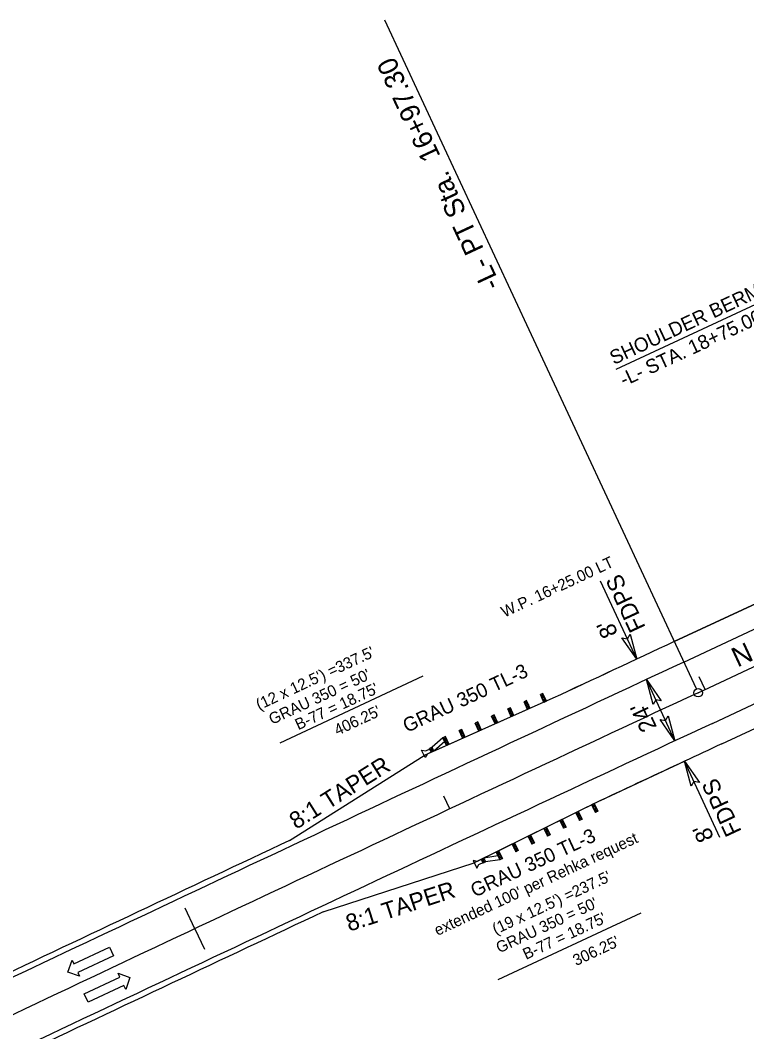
# Model space of a CAD drawing. Extents: x 2320644 to 2322941, y 921672 to 923041.
# Drawn here: x 2321170.5 to 2321428.4, y 921958.1 to 922316.8 of the extents above; entities that cross this region are included whole.
import ezdxf

# ---------------------------------------------------------------- set-up
doc = ezdxf.new("R2010")
doc.units = 0
for name, color, linetype in [('Matchline', 7, 'Continuous'), ('Matchline Text', 7, 'Continuous'), ('Prop Approach Slab', 7, 'Continuous'), ('Prop Conc Shoulder Berm Gutter', 7, 'Continuous'), ('Prop Dimension', 7, 'Continuous'), ('Prop EOT', 7, 'Continuous'), ('Prop Guardrail', 7, 'Continuous'), ('Prop Horizontal Alignment', 7, 'Continuous'), ('Prop Horizontal Alignment Tick Small', 7, 'Continuous'), ('Prop Lane Arrow CELL', 7, 'Continuous'), ('Prop North Arrow NAD83 for Plan Sheets CELL', 7, 'Continuous'), ('Sheet Sticker Exception Certification CELL', 7, 'Continuous'), ('Skimmer Basin Both CELL', 7, 'Continuous')]:
    doc.layers.add(name, color=color, linetype=linetype)

msp = doc.modelspace()

# ---------------------------------------------------------------- linework, layer by layer
at = {"layer": 'Matchline'}
msp.add_line((2321411.13, 922078.36), (2321804.4, 922261.67), dxfattribs=at)
msp.add_arc((2342535.16, 876759.76), 50000, 114.991298, 115.303471, dxfattribs=at)
at = {"layer": 'Prop Approach Slab'}
for p, q in [((2321406.06, 922089.24), (2321799.33, 922272.55)), ((2321416.2, 922067.48), (2321809.47, 922250.79))]:
    msp.add_line(p, q, dxfattribs=at)
for radius in [50012, 49988]:
    msp.add_arc((2342535.16, 876759.76), radius, 114.991298, 115.303471, dxfattribs=at)
at = {"layer": 'Prop Conc Shoulder Berm Gutter'}
for p, q in [((2321402.68, 922096.49), (2321484.21, 922134.49)), ((2321419.58, 922060.23), (2321500.59, 922097.99)), ((2321359.57, 922076.37), (2321313.84, 922056.08)), ((2321266.1, 922025.94), (2321313.84, 922056.08)), ((2321376.51, 922040.13), (2321331.66, 922018.04)), ((2321278.01, 922000.6), (2321331.66, 922018.04))]:
    msp.add_line(p, q, dxfattribs=at)
for centre, radius, start, end in [((2342535.16, 876759.76), 50020, 114.991298, 115.045792), ((2342535.16, 876759.76), 49980, 114.991298, 115.008116), ((2342522.93, 876785.96), 49951.09, 115.008105, 115.045803), ((2342535.16, 876759.76), 50014, 115.167259, 115.303471), ((2342535.16, 876759.76), 49986, 115.167259, 115.303471)]:
    msp.add_arc(centre, radius, start, end, dxfattribs=at)
at = {"layer": 'Prop Dimension'}
msp.add_line((2321410.5, 922079.72), (2321299.98, 922316.83), dxfattribs=at)
msp.add_circle((2321411.13, 922078.36), 1.5, dxfattribs=at)
at = {"layer": 'Prop EOT'}
for p, q in [((2321356.05, 922078.09), (2321355.14, 922077.68)), ((2321356.35, 922074.94), (2321355.14, 922077.68)), ((2321355.14, 922077.68), (2321356.66, 922076.72)), ((2321355.74, 922076.31), (2321356.05, 922078.09)), ((2321357.27, 922075.35), (2321356.05, 922078.09)), ((2321359.59, 922076.38), (2321316.86, 922057.41)), ((2321350.27, 922075.58), (2321349.36, 922075.17)), ((2321350.59, 922072.38), (2321349.36, 922075.17)), ((2321349.36, 922075.17), (2321350.89, 922074.18)), ((2321349.97, 922073.78), (2321350.27, 922075.58)), ((2321350.89, 922074.18), (2321349.97, 922073.78)), ((2321351.51, 922072.79), (2321350.27, 922075.58)), ((2321350.89, 922074.18), (2321350.59, 922072.38)), ((2321356.66, 922076.72), (2321355.74, 922076.31)), ((2321356.35, 922074.94), (2321355.74, 922076.31)), ((2321355.74, 922076.31), (2321357.27, 922075.35)), ((2321356.66, 922076.72), (2321356.35, 922074.94)), ((2321357.27, 922075.35), (2321356.35, 922074.94)), ((2321338.76, 922070.45), (2321337.84, 922070.05)), ((2321338.46, 922068.66), (2321338.76, 922070.45)), ((2321339.99, 922067.68), (2321338.76, 922070.45)), ((2321344.51, 922073.02), (2321343.6, 922072.61)), ((2321344.83, 922069.83), (2321343.6, 922072.61)), ((2321343.6, 922072.61), (2321345.13, 922071.63)), ((2321344.22, 922071.22), (2321344.51, 922073.02)), ((2321345.13, 922071.63), (2321344.22, 922071.22)), ((2321345.75, 922070.23), (2321344.22, 922071.22)), ((2321345.75, 922070.23), (2321344.51, 922073.02)), ((2321345.13, 922071.63), (2321344.83, 922069.83)), ((2321351.51, 922072.79), (2321349.97, 922073.78)), ((2321332.96, 922067.99), (2321332.04, 922067.58)), ((2321333.31, 922064.72), (2321332.04, 922067.58)), ((2321332.04, 922067.58), (2321333.59, 922066.56)), ((2321332.68, 922066.15), (2321332.96, 922067.99)), ((2321334.23, 922065.12), (2321332.96, 922067.99)), ((2321339.07, 922067.27), (2321337.84, 922070.05)), ((2321337.84, 922070.05), (2321339.37, 922069.07)), ((2321339.37, 922069.07), (2321338.46, 922068.66)), ((2321339.99, 922067.68), (2321338.46, 922068.66)), ((2321339.37, 922069.07), (2321339.07, 922067.27)), ((2321339.99, 922067.68), (2321339.07, 922067.27)), ((2321327.25, 922065.31), (2321326.34, 922064.9)), ((2321327.56, 922062.16), (2321326.34, 922064.9)), ((2321326.34, 922064.9), (2321327.86, 922063.94)), ((2321326.95, 922063.53), (2321327.25, 922065.31)), ((2321327.86, 922063.94), (2321326.95, 922063.53)), ((2321328.47, 922062.57), (2321326.95, 922063.53)), ((2321328.47, 922062.57), (2321327.25, 922065.31)), ((2321327.86, 922063.94), (2321327.56, 922062.16)), ((2321333.59, 922066.56), (2321332.68, 922066.15)), ((2321334.23, 922065.12), (2321332.68, 922066.15)), ((2321333.59, 922066.56), (2321333.31, 922064.72)), ((2321320.55, 922062.4), (2321316.71, 922058.99)), ((2321321.17, 922061), (2321317.32, 922057.62)), ((2321321.47, 922062.81), (2321320.55, 922062.4)), ((2321321.8, 922059.6), (2321320.55, 922062.4)), ((2321320.55, 922062.4), (2321322.09, 922061.41)), ((2321321.17, 922061), (2321321.47, 922062.81)), ((2321322.09, 922061.41), (2321321.17, 922061)), ((2321322.71, 922060.01), (2321321.17, 922061)), ((2321322.71, 922060.01), (2321321.47, 922062.81)), ((2321322.09, 922061.41), (2321321.8, 922059.6)), ((2321314.24, 922055.33), (2321313, 922057.99)), ((2321313, 922057.99), (2321314.43, 922057.71)), ((2321314.94, 922056.61), (2321314.24, 922055.33)), ((2321314.43, 922057.71), (2321316.28, 922058.58)), ((2321316.8, 922057.47), (2321314.94, 922056.61)), ((2321316.71, 922058.99), (2321315.79, 922058.58)), ((2321316.4, 922057.21), (2321315.79, 922058.58)), ((2321315.79, 922058.58), (2321317.32, 922057.62)), ((2321316.71, 922058.99), (2321316.25, 922058.79)), ((2321316.28, 922058.58), (2321316.54, 922058.02)), ((2321316.4, 922057.21), (2321316.71, 922058.99)), ((2321316.54, 922058.02), (2321316.8, 922057.47)), ((2321317.32, 922057.62), (2321316.71, 922058.99)), ((2321376.51, 922040.13), (2321334.57, 922019.47)), ((2321374.23, 922039.01), (2321373.33, 922038.56)), ((2321373.33, 922038.56), (2321374.66, 922035.87)), ((2321373.33, 922038.56), (2321373.99, 922037.22)), ((2321374.89, 922037.66), (2321373.33, 922038.56)), ((2321373.99, 922037.22), (2321374.23, 922039.01)), ((2321374.23, 922039.01), (2321375.55, 922036.32)), ((2321367.68, 922035.78), (2321369.03, 922033.04)), ((2321369.25, 922034.85), (2321367.68, 922035.78)), ((2321368.57, 922036.22), (2321368.35, 922034.41)), ((2321369.25, 922034.85), (2321368.35, 922034.41)), ((2321368.57, 922036.22), (2321369.92, 922033.48)), ((2321369.03, 922033.04), (2321369.25, 922034.85)), ((2321374.89, 922037.66), (2321373.99, 922037.22)), ((2321373.99, 922037.22), (2321375.55, 922036.32)), ((2321374.66, 922035.87), (2321374.89, 922037.66)), ((2321375.55, 922036.32), (2321374.66, 922035.87)), ((2321362.02, 922033), (2321363.37, 922030.26)), ((2321363.59, 922032.07), (2321362.02, 922033)), ((2321362.92, 922033.44), (2321362.7, 922031.63)), ((2321363.59, 922032.07), (2321362.7, 922031.63)), ((2321362.7, 922031.63), (2321364.27, 922030.7)), ((2321362.92, 922033.44), (2321364.27, 922030.7)), ((2321363.37, 922030.26), (2321363.59, 922032.07)), ((2321368.35, 922034.41), (2321369.92, 922033.48)), ((2321369.92, 922033.48), (2321369.03, 922033.04)), ((2321350.72, 922027.43), (2321352.1, 922024.61)), ((2321352.31, 922026.46), (2321350.72, 922027.43)), ((2321351.62, 922027.87), (2321351.41, 922026.02)), ((2321351.62, 922027.87), (2321353, 922025.06)), ((2321357.27, 922030.65), (2321356.37, 922030.21)), ((2321356.37, 922030.21), (2321357.71, 922027.49)), ((2321357.94, 922029.29), (2321356.37, 922030.21)), ((2321357.27, 922030.65), (2321357.04, 922028.85)), ((2321357.94, 922029.29), (2321357.04, 922028.85)), ((2321357.04, 922028.85), (2321358.61, 922027.93)), ((2321357.27, 922030.65), (2321358.61, 922027.93)), ((2321357.71, 922027.49), (2321357.94, 922029.29)), ((2321358.61, 922027.93), (2321357.71, 922027.49)), ((2321364.27, 922030.7), (2321363.37, 922030.26)), ((2321345.07, 922024.64), (2321346.39, 922021.95)), ((2321346.63, 922023.74), (2321345.07, 922024.64)), ((2321345.96, 922025.09), (2321345.73, 922023.3)), ((2321346.63, 922023.74), (2321345.73, 922023.3)), ((2321345.96, 922025.09), (2321347.29, 922022.4)), ((2321346.39, 922021.95), (2321346.63, 922023.74)), ((2321352.31, 922026.46), (2321351.41, 922026.02)), ((2321351.41, 922026.02), (2321353, 922025.06)), ((2321352.1, 922024.61), (2321352.31, 922026.46)), ((2321353, 922025.06), (2321352.1, 922024.61)), ((2321340.09, 922020.49), (2321335.02, 922019.69)), ((2321339.41, 922021.86), (2321340.77, 922019.11)), ((2321340.99, 922020.93), (2321339.41, 922021.86)), ((2321340.31, 922022.3), (2321340.09, 922020.49)), ((2321340.99, 922020.93), (2321340.09, 922020.49)), ((2321340.09, 922020.49), (2321341.66, 922019.55)), ((2321340.31, 922022.3), (2321341.66, 922019.55)), ((2321340.77, 922019.11), (2321340.99, 922020.93)), ((2321345.73, 922023.3), (2321347.29, 922022.4)), ((2321347.29, 922022.4), (2321346.39, 922021.95)), ((2321332.72, 922018.52), (2321331.29, 922018.8)), ((2321331.29, 922018.8), (2321332.54, 922016.14)), ((2321332.54, 922016.14), (2321333.24, 922017.42)), ((2321334.57, 922019.39), (2321332.72, 922018.52)), ((2321333.24, 922017.42), (2321335.09, 922018.29)), ((2321334.12, 922019.25), (2321334.78, 922017.91)), ((2321334.12, 922019.25), (2321335.68, 922018.35)), ((2321334.83, 922018.84), (2321334.57, 922019.39)), ((2321334.78, 922017.91), (2321335.02, 922019.69)), ((2321335.68, 922018.35), (2321334.78, 922017.91)), ((2321335.09, 922018.29), (2321334.83, 922018.84)), ((2321335.02, 922019.69), (2321335.68, 922018.35)), ((2321335.68, 922018.35), (2321335.23, 922018.13)), ((2321340.77, 922019.11), (2321335.68, 922018.35)), ((2321341.66, 922019.55), (2321340.77, 922019.11))]:
    msp.add_line(p, q, dxfattribs=at)
at = {"layer": 'Prop Guardrail'}
for p, q in [((2321484.21, 922134.49), (2321402.68, 922096.49)), ((2321419.58, 922060.23), (2321500.59, 922097.99)), ((2321376.51, 922040.13), (2321406.29, 922054.03))]:
    msp.add_line(p, q, dxfattribs=at)
for radius, end in [(50020, 115.04577), (49980, 115.008116)]:
    msp.add_arc((2342535.16, 876759.76), radius, 114.991298, end, dxfattribs=at)
at = {"layer": 'Prop Horizontal Alignment'}
for q in [(2321229.06, 922001.89), (2321235.88, 921987.41)]:
    msp.add_line((2321232.47, 921994.65), q, dxfattribs=at)
at = {"layer": 'Prop Horizontal Alignment Tick Small'}
for p, q in [((2321413.58, 922079.5), (2321411.46, 922084.03)), ((2321322.98, 922037.17), (2321320.86, 922041.69))]:
    msp.add_line(p, q, dxfattribs=at)
at = {"layer": 'Prop Lane Arrow CELL'}
for p, q in [((2321189.58, 921982.18), (2321202.26, 921988.09)), ((2321202.26, 921988.09), (2321203.66, 921985.1)), ((2321203.66, 921985.1), (2321190.97, 921979.19)), ((2321187.44, 921979.31), (2321188.94, 921983.54)), ((2321188.94, 921983.54), (2321189.58, 921982.18)), ((2321191.6, 921977.83), (2321187.44, 921979.31)), ((2321190.97, 921979.19), (2321191.6, 921977.83)), ((2321193.23, 921971.56), (2321205.92, 921977.48)), ((2321205.92, 921977.48), (2321205.29, 921978.84)), ((2321205.29, 921978.84), (2321209.45, 921977.36)), ((2321209.45, 921977.36), (2321207.95, 921973.13)), ((2321207.32, 921974.48), (2321194.63, 921968.57)), ((2321207.95, 921973.13), (2321207.32, 921974.48)), ((2321194.63, 921968.57), (2321193.23, 921971.56))]:
    msp.add_line(p, q, dxfattribs=at)
at = {"layer": 'Prop North Arrow NAD83 for Plan Sheets CELL'}
for p, q in [((2321509.77, 922252.58), (2321381.95, 922193)), ((2321389.37, 922090.28), (2321376.47, 922117.92)), ((2321402.9, 922061.28), (2321392.75, 922083.03)), ((2321418.88, 922027.05), (2321406.29, 922054.04))]:
    msp.add_line(p, q, dxfattribs=at)
at = {"layer": 'Sheet Sticker Exception Certification CELL'}
for points in [[(2321386.97, 922099.09), (2321389.37, 922090.28), (2321384.09, 922097.8), (2321386.03, 922097.44)], [(2321395.15, 922074.22), (2321392.75, 922083.03), (2321398.03, 922075.51), (2321396.09, 922075.87)], [(2321400.5, 922070.1), (2321402.9, 922061.28), (2321397.63, 922068.81), (2321399.56, 922068.44)], [(2321408.69, 922045.22), (2321406.29, 922054.04), (2321411.56, 922046.51), (2321409.63, 922046.88)]]:
    msp.add_lwpolyline(points, close=True, dxfattribs=at)
at = {"layer": 'Skimmer Basin Both CELL'}
for p, q in [((2321262.76, 922060.61), (2321313.54, 922084.3)), ((2321340.1, 921976.6), (2321390.88, 922000.29))]:
    msp.add_line(p, q, dxfattribs=at)

# ---------------------------------------------------------------- texts
at = {"layer": 'Matchline Text'}
msp.add_text('N 65%%d 00\' 31.3" E', height=7, rotation=24.9913, dxfattribs=at).set_placement((2321425.12, 922087.26))
at = {"layer": 'Prop Dimension'}
msp.add_text('-L- PT Sta.  16+97.30', height=7, rotation=114.9913, dxfattribs=at).set_placement((2321341.12, 922222.96))
at = {"layer": 'Prop EOT'}
for p in [(2321307.78, 922064.07), (2321331.83, 922005.67)]:
    msp.add_text('GRAU 350 TL-3', height=5, rotation=24.9913, dxfattribs=at).set_placement(p)
at = {"layer": 'Prop North Arrow NAD83 for Plan Sheets CELL'}
for s, height, rotation, p in [('SHOULDER BERM GUTTER FROM ', 5, 24.9913, (2321381.23, 922194.54)), ('-L- STA. 18+75.00 TO 18+91.83 LT. & RT.', 5, 24.9913, (2321384.82, 922186.84)), ('FDPS', 6, 115.0187, (2321392.61, 922101.54)), (" 8'", 6, 115.0187, (2321383.75, 922097.41)), ("24'", 6, 115.0187, (2321396.61, 922066.14)), ('8:1 TAPER', 6, 32.1341, (2321268.46, 922029.71)), ('FDPS', 6, 115.0187, (2321426.69, 922029.15)), (" 8'", 6, 115.0187, (2321417.83, 922025.02)), ('8:1 TAPER', 6, 18.0111, (2321287.29, 921993.58))]:
    msp.add_text(s, height=height, rotation=rotation, dxfattribs=at).set_placement(p)
at = {"layer": 'Skimmer Basin Both CELL'}
for s, p in [('W.P. 16+25.00 LT', (2321342.35, 922104.96)), ("(12 x 12.5') =337.5'", (2321255.32, 922072.08)), ("GRAU 350 = 50'", (2321259.91, 922066.93)), ("B-77 = 18.75'", (2321269.21, 922065.01)), ("406.25'", (2321283.1, 922063.07)), ("extended 100' per Rehka request", (2321318.62, 921992.06)), ("(19 x 12.5') =237.5'", (2321339.23, 921992.49)), ("GRAU 350 = 50'", (2321340.56, 921985.9)), ("B-77 = 18.75'", (2321350.05, 921983.6)), ("306.25'", (2321367.81, 921981.39))]:
    msp.add_text(s, height=4, rotation=24.9913, dxfattribs=at).set_placement(p)

doc.saveas('drawing.dxf')
